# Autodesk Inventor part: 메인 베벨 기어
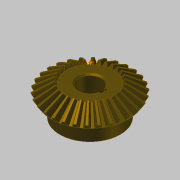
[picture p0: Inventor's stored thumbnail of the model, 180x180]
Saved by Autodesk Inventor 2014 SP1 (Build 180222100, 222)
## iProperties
Created: 2016-04
Part Number: 메인 베벨 기어
Material: 강철, 탄소
Document SubType Name: Modeling
Designer: mdu
Categories: <?xml version="1.0" encoding="UTF-16"?> <MemberInstance><Categories><FamilyTemplate><FamilyTemplateParameter ValueType="xs:double" Id="1" ObjectReferenceKey="da
Mass: 269.926 g
Surface Area: 108.837 cm^2
Volume: 34.2981 cm^3
Density: 7.87 g/cm^3
Appearance: 얼룩무늬
CustomPartVersion: 1
Author: mdu
Revision Number: 1
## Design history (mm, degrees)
node "맨 위 점"
node "메쉬 평면2"
sketch "톱니 본체 스케치"
  geometry: L1 (0, 0)-(28.669, -21.997); L2 (28.669, -21.997)-(31.109, -18.336); L3 (31.109, -18.336)-(0, 0); L4 (30, -20)-(0, 0); L5 (17.219, -13.212)-(18.685, -11.013); L6 (28.669, -21.997)-(17.219, -13.212); L7 (31.109, -18.336)-(18.685, -11.013); L8 (0, -39.387)-(0, 6.564) reference; L9 (0, -20)-(31.109, -20)
  constraints: 16 end point, 4 point on line, 3 perpendicular, 2 collinear, 1 horizontal alignment, 1 vertical alignment
  dimensions: "d0" = 60 diameter of L4.start L8 (= da_de); "d1" = 57.33744 diameter of L1.end L8 (= da_dfe); "d2" = 62.2188 diameter of L2.end L8 (= da_dae); "d3" = 14.4 distance between parallel lines of L2 L5 (= da_b); "d4" = 18.3359 vertical distance of L2.end L1.start (= da_ve)
revolve "톱니 본체" sketch "톱니 본체 스케치" stored, may be unused: angle "d5" = 90 deg
node "시작점"
node "톱니 평면"
sketch "시작 스케치"
  geometry: L1 (0, -23.505)-(0, 10.645) reference; L2 (-0.709, -2.928)-(0.709, -2.928); A1 r 19.188 centre (-19.457, -7.014) between (-0.709, -2.928) and (-3.232, 3.229); A2 r 19.188 centre (19.457, -7.014) between (3.232, 3.229) and (0.709, -2.928); A3 r 57.403 centre (0, -54.083) between (3.232, 3.229) and (-3.232, 3.229); 1 further point
  constraints: 6 point on circle, 3 centre point, 3 symmetric about line, 2 end point, 1 coincident, 1 perpendicular, 1 other
  dimensions: "d7" = 19.18795 radius of A1 (= fd_rr); "d8" = 19.45712 horizontal distance of point (0, -54.083) A1.centre (= fd_x); "d9" = 47.06905 vertical distance of point (0, -54.083) A1.centre (= fd_y); "d57" = 57.40327 radius of A3 (= 0.5 x fd_dva + 0.3 x da_he); "d58" = 51.15527 distance from line of A3.centre L2 (= 0.5 x fd_dva - 1.12 x da_he)
node "끝점"
  node "끝 평면"
sketch "3D 스케치 오른쪽"
  node "Helical Curve Right" dims "d65" = 229.90621 (computed from da_dm, da_delta, da_beta), "d66" = 31.5, "d67" = 60 (= da_de), "d68" = -9.82794 (= -da_delta), "d69" = 8.10972 (computed from fd_loft, da_delta)
node "끝 평면 오른쪽"
sketch "끝 스케치 오른쪽"
  geometry: L1 (0, -41.54)-(0, 13.178) reference; L2 (-0.422, -1.69)-(0.422, -1.69); A1 r 11.427 centre (-11.587, -4.123) between (-0.422, -1.69) and (-1.925, 1.977); A2 r 11.427 centre (11.587, -4.123) between (1.925, 1.977) and (0.422, -1.69); A3 r 34.184 centre (0, -32.153) between (1.925, 1.977) and (-1.925, 1.977); 1 further point
  constraints: 6 point on circle, 3 centre point, 3 symmetric about line, 2 end point, 1 coincident, 1 perpendicular, 1 other
  dimensions: "d70" = 11.58699 horizontal distance of A3.centre A1.centre (computed from fd_x, fd_ratio); "d71" = 28.03028 vertical distance of point (0, -32.153) A1.centre (computed from fd_y, fd_ratio); "d72" = 11.4267 radius of A1 (computed from fd_rr, fd_ratio); "d73" = 30.46369 distance from line of point (0, -32.153) L2 (computed from d58, fd_ratio); "d74" = 34.18446 radius of A3 (computed from d57, fd_ratio)
feature "로프트 오른쪽" sketch "끝 스케치 오른쪽" dims "d75" = 0, "d77" = 0, "d79" = 0, "d80" = 90 deg, "d85" = 20, "d92" = 90 deg, "d93" = 90 deg, "da_teethtype" = 0 [user parameter]
sketch "3D 스케치 왼쪽"
  node "Helical Curve Left" dims "d26" = 229.90621 (computed from da_dm, da_delta, da_beta), "d27" = 8.10972 (computed from fd_loft, da_delta), "d28" = 60 (= da_de), "d29" = -9.82794 (= -da_delta)
node "끝 평면 왼쪽"
sketch "끝 스케치 왼쪽" dims "d56" = 10.3728 (derived)
  geometry: L1 (0, -43.753)-(0, 15.405) reference; L2 (-0.422, -1.678)-(0.422, -1.678); A1 r 11.427 centre (-11.587, -4.111) between (-0.422, -1.678) and (-1.925, 1.988); A2 r 11.427 centre (11.587, -4.111) between (1.925, 1.988) and (0.422, -1.678); A3 r 34.184 centre (0, -32.142) between (1.925, 1.988) and (-1.925, 1.988); 2 further points; 1 other entity
  constraints: 6 point on circle, 3 centre point, 3 symmetric about line, 2 end point, 1 coincident, 2 other
  dimensions: "d30" = 11.4267 radius of A1 (computed from fd_rr, fd_ratio); "d31" = 11.58699 horizontal distance of point (0, -32.142) A1.centre (computed from fd_x, fd_ratio); "d32" = 28.03028 vertical distance of A1.centre point (0, -32.142) (computed from fd_y, fd_ratio); "d61" = 34.18446 radius of A3 (computed from d57, fd_ratio); "d62" = 30.46369 distance from line of point (0, -32.142) L2 (computed from d58, fd_ratio)
feature "로프트 왼쪽" sketch "끝 스케치 왼쪽" dims "d35" = 0, "d37" = 0, "d39" = 0, "d40" = 90 deg, "d84" = 10, "d90" = 90 deg, "d91" = 90 deg, "da_teethtype" = 0 [user parameter]
sketch "본체 스케치"
  geometry: L1 (0, -35.038)-(0, -19.531) reference; L2 (28.669, -21.997)-(17.219, -13.212) reference; L3 (17.219, -13.212)-(0, -13.212); L4 (28.669, -21.997)-(0, -21.997)
  constraints: 4 end point, 2 perpendicular, 2 point on line
revolve "본체 고정" sketch "본체 스케치" stored, may be unused: angle "d46" = 90 deg
feature "피치 지름" dims angle "d47" = 90 deg
sketch "스케치8"
  geometry: C1 r 22.5 at (0, 0); 1 further point
  constraints: 1 centre point, 1 coincident
  dimensions: "d94" = 45 diameter of C1
extrude "돌출1" join sketch "스케치8" distance "d95" = 13; taper "d96" = 0 deg
sketch "스케치9"
  geometry: 1 further point
hole "구멍1" sketch "스케치9" at (0, 0) diameter "d97" = 17; stored, may be unused: countersink angle "d101" = 90 deg, drill point angle "d103" = 118 deg; dims "d98" = 6, "d99" = 4, "d100" = 2, "d102" = 8
sketch "스케치10"
  geometry: L1 (8.124, 2.5)-(10.8, 2.5); L2 (10.8, 2.5)-(10.8, -2.5); L3 (10.8, -2.5)-(8.124, -2.5); A1 r 8.5 centre (0, 0) between (8.124, 2.5) and (8.124, -2.5) reference; 1 further point
  constraints: 6 end point, 2 parallel, 2 point on circle, 1 horizontal, 1 perpendicular
  dimensions: "d104" = 5 distance of L1.end L2.end; "d112" = 19.3 dimension on A1 L2
extrude "돌출2" cut sketch "스케치10" stored distance "d106" = 10; taper "d107" = 0 deg
chamfer "모따기1" distance "d108" = 1; stored, may be unused: second distance "d109" = 2, angle "d110" = 45 deg
fillet "모깎기1" dims "d111" = 2
body "Solid1"
feature "로프트" dims "d17" = 0, "d18" = 90 deg, "d19" = 0, "d20" = 90 deg, "d89" = 0, "da_teethtype" = 0 [user parameter]
pattern_circular "원형 패턴" dims angle "d22" = 360 deg, "d88" = 0, "da_teethtype" = 0 [user parameter]
pattern_circular "원형 패턴 오른쪽" dims angle "d82" = 360 deg, "da_teethtype" = 0 [user parameter]
pattern_circular "원형 패턴 왼쪽" dims angle "d42" = 360 deg, "da_teethtype" = 0 [user parameter]
sketch "끝 스케치"
  geometry: L1 (0, -15.359)-(0, 6.983) reference; L2 (-0.422, -1.69)-(0.422, -1.69); A1 r 11.427 centre (-11.587, -4.123) between (-0.422, -1.69) and (-1.925, 1.977); A2 r 11.427 centre (11.587, -4.123) between (1.925, 1.977) and (0.422, -1.69); A3 r 34.184 centre (0, -32.153) between (1.925, 1.977) and (-1.925, 1.977); 1 further point
  constraints: 6 point on circle, 3 centre point, 3 symmetric about line, 2 end point, 1 coincident, 1 other
  dimensions: "d12" = 11.4267 radius of A1 (computed from fd_rr, fd_ratio); "d15" = 11.58699 horizontal distance of A1.centre point (0, -32.153) (computed from fd_x, fd_ratio); "d16" = 28.03028 vertical distance of A1.centre point (0, -32.153) (computed from fd_y, fd_ratio); "d59" = 34.18446 radius of A3 (computed from d57, fd_ratio); "d60" = 30.46369 distance from line of A3.centre L2 (computed from d58, fd_ratio)
sketch "Sketch6"
  geometry: L1 (30, -20)-(0, 0) reference; L2 (0, -37.8)-(0, 6.3) reference
body "Srf1"
other parameters: "da_b" = 14.4 [user parameter; used in 2 equation terms], "da_de" = 60 [user parameter; used in 4 equation terms], "da_dae" = 62.2188 [user parameter; used in 2 equation terms], "da_dfe" = 57.33744 [user parameter; used in 1 equation term], "da_le" = 36.05551 [user parameter; used in 1 equation term], "da_omega" = 90 deg [user parameter; used in 1 equation term], "da_beta" = 0 [user parameter; used in 2 equation terms], "da_delta" = 9.82794 [user parameter; used in 8 equation terms], "da_alpha" = 20 deg [user parameter; used in 2 equation terms], "da_he" = 4.4 [user parameter; used in 4 equation terms], "da_ve" = 18.3359 [user parameter; used in 1 equation term], "fd_dv" = 108.16654 (computed from da_de, da_delta) [user parameter; used in 1 equation term], "fd_dva" = 112.16654 (computed from da_dae, da_delta) [user parameter; used in 3 equation terms], "fd_dvb" = 101.6433 (computed from fd_dv, da_alpha) [user parameter; used in 2 equation terms], "da_zv" = 540.83269 [user parameter; used in 1 equation term], "fd_loft" = 14.62 (= da_b + 0.05 x da_he) [user parameter; used in 4 equation terms], "fd_ratio" = 5.95514 (computed from da_le, fd_loft) [user parameter; used in 15 equation terms], "fd_rr" = 19.18795 (computed from fd_dd, fd_dvb) [user parameter; used in 6 equation terms], "fd_angle" = 0.29367 (computed from da_zv) [user parameter; used in 4 equation terms], "fd_x1" = 1.58802 (computed from da_dvw, fd_angle) [user parameter; used in 1 equation term], "fd_y1" = 54.05995 (computed from da_dvw, fd_angle) [user parameter; used in 1 equation term], "fd_x2" = 17.8691 (computed from fd_rr, fd_angle2, fd_angle) [user parameter; used in 1 equation term], "fd_y2" = 6.9909 (computed from fd_rr, fd_angle2, fd_angle) [user parameter; used in 1 equation term], "fd_x" = 19.45712 (= fd_x1 + fd_x2) [user parameter; used in 4 equation terms], "fd_y" = 47.06905 (= fd_y1 - fd_y2) [user parameter; used in 4 equation terms], "fd_angle2" = 3.43555 (computed from fd_dvb, fd_dd, da_alpha) [user parameter; used in 2 equation terms], "fd_dd" = 108.64654 (= fd_dva - 0.8 x da_he) [user parameter; used in 2 equation terms], "da_dvw" = 108.16654 [user parameter; used in 2 equation terms], "d11" = 14.62 (= fd_loft), "da_dm" = 48.01848 [user parameter; used in 2 equation terms], "da_x" = 0 [user parameter], "da_m" = 2 [user parameter], "d48" = 0, "d49" = 0, "d50" = 90 deg (= da_omega), "d51" = 6 deg (computed from da_z), "d52" = 0, "d53" = 0, "d54" = 0
